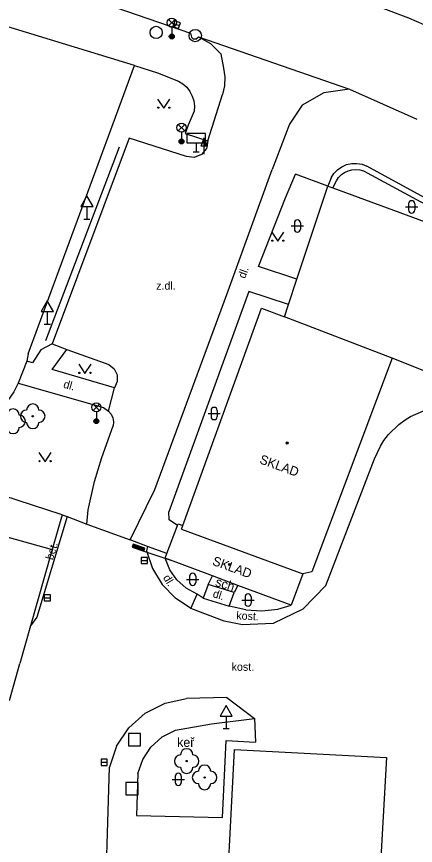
# Model space of a CAD drawing. Extents: x -598233 to -596890, y -1157848 to -1156431.
# Drawn here: x -598107.9 to -598075.5, y -1157490.1 to -1157422.8 of the extents above; entities that cross this region are included whole.
import ezdxf

# ---------------------------------------------------------------- set-up
doc = ezdxf.new("R2010")
doc.units = 0
for name, color, linetype in [('Level 10', 7, 'Continuous'), ('Level 11', 7, 'Continuous'), ('Level 22', 7, 'Continuous'), ('Level 25', 7, 'Continuous'), ('Level 26', 7, 'Continuous'), ('Level 27', 7, 'Continuous'), ('Level 33', 7, 'Continuous'), ('Level 34', 7, 'Continuous'), ('Level 36', 7, 'Continuous'), ('Level 39', 7, 'Continuous'), ('Level 40', 7, 'Continuous'), ('Level 41', 7, 'Continuous'), ('Level 42', 7, 'Continuous'), ('Level 5', 7, 'Continuous'), ('Level 7', 7, 'Continuous'), ('Level 8', 7, 'Continuous')]:
    doc.layers.add(name, color=color, linetype=linetype)

msp = doc.modelspace()

# ---------------------------------------------------------------- linework, layer by layer
at = {"layer": 'Level 10'}
for points in [[(-598122.65, -1157415.04), (-598121.35, -1157414.91), (-598120.33, -1157414.94), (-598106.78, -1157419.65), (-598093.77, -1157424.14)], [(-598076.03, -1157422.91), (-598078.56, -1157421.96)], [(-598073.53, -1157423.99), (-598076.03, -1157422.91)], [(-598093.77, -1157424.14), (-598093.71, -1157424.45)], [(-598093.35, -1157424.62), (-598093.54, -1157424.63), (-598093.71, -1157424.45)], [(-598093.35, -1157424.62), (-598093.12, -1157424.44)], [(-598093.12, -1157424.44), (-598092.16, -1157424.96)], [(-598092.16, -1157424.96), (-598091.32, -1157425.82)], [(-598091.32, -1157425.82), (-598091.09, -1157426.97)], [(-598091.09, -1157426.9699), (-598090.99, -1157427.69), (-598091.02, -1157428.4099), (-598091.19, -1157429.12)], [(-598080.85, -1157428.69), (-598082.95, -1157428.98)], [(-598080.85, -1157428.69), (-598075.38, -1157431.12)], [(-598092.38, -1157432.87), (-598091.19, -1157429.12)], [(-598082.95, -1157428.98), (-598084.71, -1157429.98)], [(-598084.71, -1157429.98), (-598085.73, -1157431.52), (-598087.13, -1157435.2)], [(-598094.1, -1157434.15), (-598098.77, -1157432.65), (-598105.01, -1157449.35)], [(-598092.48, -1157433.5), (-598092.88, -1157433.99), (-598093.47, -1157434.23), (-598094.1, -1157434.15)], [(-598092.38, -1157432.87), (-598092.48, -1157433.5)], [(-598090.83, -1157445.34), (-598087.13, -1157435.2)], [(-598096.67, -1157461.19), (-598090.83, -1157445.34)], [(-598105.01, -1157449.35), (-598103.84, -1157449.82)], [(-598103.84, -1157449.82), (-598100.41, -1157451.03)], [(-598100.41, -1157451.03), (-598099.98, -1157451.38), (-598099.74, -1157451.87)], [(-598099.74, -1157451.87), (-598099.73, -1157452.42), (-598099.95, -1157452.92)], [(-598100.43, -1157454.82), (-598099.95, -1157452.92)], [(-598100.43, -1157454.82), (-598100.23, -1157455.08), (-598100.1, -1157455.38), (-598100.05, -1157455.7), (-598100.07, -1157456.03)], [(-598078.83, -1157458.71), (-598078.34, -1157457.6599), (-598078.07, -1157457.2), (-598077.68, -1157456.7199), (-598076.85, -1157455.9099), (-598076.34, -1157455.53), (-598075.9, -1157455.26), (-598074.85, -1157454.79), (-598073.73, -1157454.51), (-598072.58, -1157454.44), (-598071.44, -1157454.57)], [(-598102.21, -1157464.01), (-598102.09, -1157462.85), (-598101.59, -1157460.53), (-598100.98, -1157458.58), (-598100.07, -1157456.03)], [(-598082.77, -1157468.99), (-598078.83, -1157458.71)], [(-598098.68, -1157465.28), (-598096.67, -1157461.19)], [(-598103.81, -1157463.38), (-598106.28, -1157471.55), (-598106.77, -1157472.27)], [(-598097.26, -1157465.81), (-598097.36, -1157466.18)], [(-598097.36, -1157466.18), (-598096.86, -1157467.61), (-598096.07, -1157468.91), (-598095.01, -1157470.01)], [(-598082.77, -1157468.99), (-598084.6599, -1157470.9), (-598087.07, -1157472.07)], [(-598093.75, -1157470.85), (-598095.01, -1157470.01)], [(-598089.54, -1157472.19), (-598091.05, -1157471.89), (-598093.75, -1157470.85)], [(-598087.07, -1157472.07), (-598089.54, -1157472.19)], [(-598099.78, -1157482.03), (-598098.79, -1157480.54), (-598097.45, -1157479.35), (-598095.85, -1157478.54), (-598094.1, -1157478.16)], [(-598090.82, -1157478.08), (-598094.1, -1157478.16)], [(-598099.78, -1157482.03), (-598100.36, -1157483.73)], [(-598100.77, -1157497.17), (-598100.36, -1157483.73)]]:
    msp.add_lwpolyline(points, dxfattribs=at)
at = {"layer": 'Level 11'}
for points in [[(-598093.12, -1157424.44), (-598080.85, -1157428.69)], [(-598098.33, -1157426.76), (-598096.46, -1157427.35), (-598094.75, -1157428.02)], [(-598094.75, -1157428.02), (-598094.4, -1157428.25), (-598094.09, -1157428.53), (-598093.83, -1157428.86), (-598093.64, -1157429.24), (-598093.51, -1157429.63), (-598093.45, -1157430.05), (-598093.4699, -1157430.4699)], [(-598093.47, -1157430.47), (-598093.98, -1157431.61)], [(-598093.98, -1157431.61), (-598094.2, -1157432.28)], [(-598094.2, -1157432.28), (-598092.38, -1157432.87)], [(-598082.34, -1157435.88), (-598082.12, -1157435.53), (-598081.82, -1157435.23), (-598081.48, -1157434.98), (-598081.09, -1157434.81), (-598080.68, -1157434.7199), (-598080.26, -1157434.71), (-598079.84, -1157434.78), (-598079.45, -1157434.93)], [(-598081.92, -1157436.12), (-598081.74, -1157435.85), (-598081.52, -1157435.62), (-598081.26, -1157435.44), (-598080.9699, -1157435.31), (-598080.67, -1157435.23), (-598080.35, -1157435.2), (-598080.03, -1157435.23), (-598079.73, -1157435.32)], [(-598079.73, -1157435.32), (-598068.09, -1157441.59)], [(-598067.87, -1157441.24), (-598079.45, -1157434.93)], [(-598085.13, -1157444.11), (-598088.24, -1157443.07), (-598086.06, -1157437.51), (-598085.25, -1157435.58)], [(-598082.61, -1157436.55), (-598085.25, -1157435.58)], [(-598082.34, -1157435.88), (-598082.61, -1157436.55)], [(-598082.2, -1157436.7), (-598081.92, -1157436.12)], [(-598089.04, -1157445.1), (-598095.55, -1157462.99)], [(-598085.82, -1157446.17), (-598089.04, -1157445.1)], [(-598105.01, -1157449.35), (-598105.94, -1157449.85), (-598106.62, -1157450.9), (-598107.09, -1157450.76)], [(-598099.95, -1157452.92), (-598105.02, -1157451.44), (-598103.84, -1157449.82)], [(-598107.78, -1157452.55), (-598100.86, -1157454.53), (-598100.43, -1157454.82)], [(-598094.83, -1157464.11), (-598095.51, -1157463.64), (-598095.55, -1157462.99)], [(-598113.58, -1157463.69), (-598105.02, -1157466.07)], [(-598093.25, -1157469.68), (-598094.14, -1157469.2), (-598094.89, -1157468.53), (-598095.47, -1157467.7), (-598095.85, -1157466.77)], [(-598092.33, -1157468.89), (-598091.99, -1157468.2)], [(-598092.33, -1157468.89), (-598092.74, -1157470.01), (-598093.25, -1157469.68)], [(-598090.24, -1157469.55), (-598092.33, -1157468.89)], [(-598089.93, -1157468.97), (-598090.24, -1157469.55)], [(-598093.75, -1157470.85), (-598093.25, -1157469.68)], [(-598089.28, -1157470.97), (-598090.63, -1157470.67), (-598090.24, -1157469.55)], [(-598092.74, -1157470.01), (-598090.63, -1157470.67)], [(-598089.28, -1157470.97), (-598087.98, -1157471.03), (-598086.69, -1157470.91), (-598085.6, -1157470.58)], [(-598090.82, -1157478.08), (-598088.59, -1157479.77), (-598088.5, -1157481.7)], [(-598095.01, -1157480.72), (-598092.07, -1157480.21), (-598088.59, -1157479.77)], [(-598098.05, -1157484.26), (-598097.65, -1157483.11), (-598096.99, -1157482.1), (-598096.09, -1157481.28), (-598095.01, -1157480.72)], [(-598098.05, -1157484.26), (-598098.18, -1157487.66), (-598091.19, -1157487.83), (-598090.87, -1157481.58), (-598088.5, -1157481.7)]]:
    msp.add_lwpolyline(points, dxfattribs=at)
at = {"layer": 'Level 22'}
for centre in [(-598106.6, -1157455.24), (-598094.09, -1157483.24), (-598092.63, -1157484.57)]:
    msp.add_circle(centre, 0.05, dxfattribs=at)
for centre, start, end in [((-598106.6, -1157454.74), 0, 180), ((-598108.2, -1157455.15), 0, 180), ((-598107.1, -1157455.24), 90, 270), ((-598106.1, -1157455.24), 270, 90), ((-598107.7, -1157455.65), 270, 90), ((-598108.2, -1157456.15), 180, 0), ((-598106.6, -1157455.74), 180, 0), ((-598094.09, -1157482.74), 0, 180), ((-598094.59, -1157483.24), 90, 270), ((-598093.59, -1157483.24), 270, 90), ((-598094.09, -1157483.74), 180, 0), ((-598092.63, -1157484.07), 0, 180), ((-598093.13, -1157484.57), 90, 270), ((-598092.13, -1157484.57), 270, 90), ((-598092.63, -1157485.07), 180, 0)]:
    msp.add_arc(centre, 0.5, start, end, dxfattribs=at)
at = {"layer": 'Level 25'}
for p, q in [((-598092.922, -1157433.298), (-598092.67, -1157432.624)), ((-598092.67, -1157433.298), (-598092.922, -1157433.298)), ((-598092.67, -1157433.95), (-598092.67, -1157433.3))]:
    msp.add_line(p, q, dxfattribs=at)
for points in [[(-598092.42, -1157433.3), (-598092.67, -1157433.3), (-598092.67, -1157432.624), (-598092.67, -1157432.624)], [(-598092.477, -1157433.26), (-598092.63, -1157433.26), (-598092.63, -1157432.847)], [(-598092.535, -1157433.22), (-598092.59, -1157433.22), (-598092.59, -1157433.071)]]:
    msp.add_lwpolyline(points, close=True, dxfattribs=at)
at = {"layer": 'Level 26'}
for points in [[(-598098.83, -1157482.01), (-598097.83, -1157482.01), (-598097.83, -1157481.01), (-598098.83, -1157481.01)], [(-598099.03, -1157485.98), (-598098.03, -1157485.98), (-598098.03, -1157484.98), (-598099.03, -1157484.98)]]:
    msp.add_lwpolyline(points, close=True, dxfattribs=at)
at = {"layer": 'Level 27'}
for p, q in [((-598095.1358, -1157423.357), (-598094.6642, -1157423.523)), ((-598097.78, -1157466.96), (-598097.28, -1157466.96)), ((-598105.66, -1157469.98), (-598105.16, -1157469.98)), ((-598101.05, -1157483.34), (-598100.55, -1157483.34))]:
    msp.add_line(p, q, dxfattribs=at)
for points in [[(-598095.2188, -1157423.5928), (-598094.7472, -1157423.7588), (-598094.5812, -1157423.2872), (-598095.0528, -1157423.1212)], [(-598097.78, -1157467.21), (-598097.28, -1157467.21), (-598097.28, -1157466.71), (-598097.78, -1157466.71)], [(-598105.66, -1157470.23), (-598105.16, -1157470.23), (-598105.16, -1157469.73), (-598105.66, -1157469.73)], [(-598101.05, -1157483.59), (-598100.55, -1157483.59), (-598100.55, -1157483.09), (-598101.05, -1157483.09)]]:
    msp.add_lwpolyline(points, close=True, dxfattribs=at)
for centre in [(-598096.57, -1157424.07), (-598093.39, -1157424.33)]:
    msp.add_circle(centre, 0.5, dxfattribs=at)
at = {"layer": 'Level 33'}
for p, q in [((-598095.565, -1157423.5499), (-598095.035, -1157423.0199)), ((-598095.565, -1157423.0199), (-598095.035, -1157423.5499)), ((-598095.3, -1157423.6599), (-598095.3, -1157424.4099)), ((-598094.775, -1157432.07), (-598094.245, -1157431.54)), ((-598094.775, -1157431.54), (-598094.245, -1157432.07)), ((-598094.51, -1157432.18), (-598094.51, -1157432.93)), ((-598101.695, -1157454.78), (-598101.165, -1157454.25)), ((-598101.695, -1157454.25), (-598101.165, -1157454.78)), ((-598101.43, -1157454.89), (-598101.43, -1157455.64)), ((-598097.5738, -1157466.1837), (-598095.2084, -1157466.9929))]:
    msp.add_line(p, q, dxfattribs=at)
for points in [[(-598098.52, -1157465.86), (-598097.5738, -1157466.1837), (-598097.4929, -1157465.9472), (-598098.4391, -1157465.6235)], [(-598098.4565, -1157465.8289), (-598097.605, -1157466.1202), (-598097.5564, -1157465.9783), (-598098.408, -1157465.687)], [(-598098.393, -1157465.7978), (-598097.6361, -1157466.0567), (-598097.6199, -1157466.0094), (-598098.3768, -1157465.7504)]]:
    msp.add_lwpolyline(points, close=True, dxfattribs=at)
for centre, radius in [((-598095.3, -1157423.2849), 0.375), ((-598095.3, -1157424.4099), 0.2), ((-598095.3, -1157424.4099), 0.1445), ((-598095.3, -1157424.4099), 0.0876), ((-598094.51, -1157431.805), 0.375), ((-598094.51, -1157432.93), 0.2), ((-598094.51, -1157432.93), 0.1445), ((-598094.51, -1157432.93), 0.0876), ((-598101.43, -1157454.515), 0.375), ((-598101.43, -1157455.64), 0.2), ((-598101.43, -1157455.64), 0.1445), ((-598101.43, -1157455.64), 0.0876)]:
    msp.add_circle(centre, radius, dxfattribs=at)
at = {"layer": 'Level 34'}
for p, q in [((-598093.32, -1157433.03), (-598093.32, -1157433.78)), ((-598093.57, -1157433.78), (-598093.07, -1157433.78)), ((-598102.2, -1157438.212), (-598102.2, -1157439.23)), ((-598102.45, -1157439.23), (-598101.95, -1157439.23)), ((-598105.42, -1157446.732), (-598105.42, -1157447.75)), ((-598105.67, -1157447.75), (-598105.17, -1157447.75)), ((-598090.88, -1157479.582), (-598090.88, -1157480.6)), ((-598091.13, -1157480.6), (-598090.63, -1157480.6))]:
    msp.add_line(p, q, dxfattribs=at)
for points in [[(-598094.07, -1157433.03), (-598092.57, -1157433.03), (-598092.57, -1157432.28), (-598094.07, -1157432.28)], [(-598102.7, -1157438.212), (-598101.7, -1157438.212), (-598102.2, -1157437.346)], [(-598105.92, -1157446.732), (-598104.92, -1157446.732), (-598105.42, -1157445.866)], [(-598091.38, -1157479.582), (-598090.38, -1157479.582), (-598090.88, -1157478.716)]]:
    msp.add_lwpolyline(points, close=True, dxfattribs=at)
at = {"layer": 'Level 36'}
for p, q in [((-598076.056, -1157437.986), (-598076.056, -1157438.486)), ((-598075.556, -1157437.986), (-598075.556, -1157438.486)), ((-598076.306, -1157438.236), (-598075.306, -1157438.236)), ((-598085.336, -1157439.536), (-598085.336, -1157440.036)), ((-598084.836, -1157439.536), (-598084.836, -1157440.036)), ((-598085.586, -1157439.786), (-598084.586, -1157439.786)), ((-598092.356, -1157455.016), (-598091.356, -1157455.016)), ((-598092.106, -1157454.766), (-598092.106, -1157455.266)), ((-598091.606, -1157454.766), (-598091.606, -1157455.266)), ((-598094.106, -1157468.486), (-598093.106, -1157468.486)), ((-598093.856, -1157468.236), (-598093.856, -1157468.736)), ((-598093.356, -1157468.236), (-598093.356, -1157468.736)), ((-598089.596, -1157470.166), (-598088.596, -1157470.166)), ((-598089.346, -1157469.916), (-598089.346, -1157470.416)), ((-598088.846, -1157469.916), (-598088.846, -1157470.416)), ((-598095.026, -1157484.476), (-598095.026, -1157484.976)), ((-598094.526, -1157484.476), (-598094.526, -1157484.976)), ((-598095.276, -1157484.726), (-598094.276, -1157484.726))]:
    msp.add_line(p, q, dxfattribs=at)
for points in [[(-598096.45, -1157429.48), (-598095.95, -1157430.23), (-598095.45, -1157429.48)], [(-598087.18, -1157440.28), (-598086.68, -1157441.03), (-598086.18, -1157440.28)], [(-598102.86, -1157451.02), (-598102.36, -1157451.77), (-598101.86, -1157451.02)], [(-598106.1, -1157458.19), (-598105.6, -1157458.94), (-598105.1, -1157458.19)]]:
    msp.add_lwpolyline(points, dxfattribs=at)
for centre in [(-598096.4002, -1157430.1798), (-598095.5008, -1157430.1798), (-598087.1302, -1157440.9798), (-598086.2308, -1157440.9798), (-598102.8102, -1157451.7198), (-598101.9108, -1157451.7198), (-598106.0502, -1157458.8898), (-598105.1508, -1157458.8898)]:
    msp.add_circle(centre, 0.05, dxfattribs=at)
for centre, start, end in [((-598075.8057, -1157437.9863), 0, 180), ((-598075.8057, -1157438.4863), 180, 0), ((-598085.0857, -1157439.5363), 0, 180), ((-598085.0857, -1157440.0363), 180, 0), ((-598091.8557, -1157454.7663), 0, 180), ((-598091.8557, -1157455.2663), 180, 0), ((-598093.6057, -1157468.2363), 0, 180), ((-598093.6057, -1157468.7363), 180, 0), ((-598089.0957, -1157469.9163), 0, 180), ((-598089.0957, -1157470.4163), 180, 0), ((-598094.7757, -1157484.4763), 0, 180), ((-598094.7757, -1157484.9763), 180, 0)]:
    msp.add_arc(centre, 0.25, start, end, dxfattribs=at)
at = {"layer": 'Level 39'}
for centre, radius in [((-598085.92, -1157457.42), 0.09), ((-598085.92, -1157457.42), 0.0398), ((-598090.61, -1157467.28), 0.09), ((-598090.61, -1157467.28), 0.0398)]:
    msp.add_circle(centre, radius, dxfattribs=at)
at = {"layer": 'Level 5'}
for points in [[(-598086.15, -1157447.17), (-598085.82, -1157446.17), (-598085.13, -1157444.11), (-598082.61, -1157436.55)], [(-598082.61, -1157436.55), (-598082.2, -1157436.7)], [(-598082.2, -1157436.7), (-598068.2199, -1157441.83)], [(-598094.39, -1157464.11), (-598088.02, -1157446.4699)], [(-598088.02, -1157446.4699), (-598086.15, -1157447.17)], [(-598077.4, -1157450.53), (-598086.15, -1157447.17)], [(-598077.4, -1157450.53), (-598083.9099, -1157467.88)], [(-598066.08, -1157455.02), (-598077.4, -1157450.53)], [(-598095.85, -1157466.77), (-598095.7, -1157466.39), (-598094.83, -1157464.11), (-598094.78, -1157463.9699)], [(-598094.78, -1157463.9699), (-598094.39, -1157464.11)], [(-598094.5, -1157464.4099), (-598094.39, -1157464.11)], [(-598094.5, -1157464.4099), (-598084.6599, -1157468.04)], [(-598085.6, -1157470.58), (-598089.93, -1157468.97), (-598091.99, -1157468.2), (-598095.85, -1157466.77)], [(-598084.6599, -1157468.04), (-598085.6, -1157470.58)], [(-598083.9099, -1157467.88), (-598084.6599, -1157468.04)], [(-598091.03, -1157498.54), (-598090.21, -1157482.31)], [(-598090.21, -1157482.31), (-598077.85, -1157482.94)], [(-598077.85, -1157482.94), (-598078.74, -1157498.76)]]:
    msp.add_lwpolyline(points, dxfattribs=at)
at = {"layer": 'Level 7'}
for points in [[(-598098.33, -1157426.76), (-598124.68, -1157418.7)], [(-598100.25, -1157431.97), (-598098.33, -1157426.76)], [(-598106.97, -1157450.17), (-598100.25, -1157431.97)], [(-598105.53, -1157449.08), (-598099.56, -1157433.36)], [(-598107.78, -1157452.55), (-598108.14, -1157453.25), (-598109.38, -1157455.01), (-598111.63, -1157457.09)], [(-598104.22, -1157463.24), (-598112.64, -1157460.5)], [(-598104.22, -1157463.24), (-598105.02, -1157466.07), (-598106.77, -1157472.27), (-598107.66, -1157475.33)], [(-598104.22, -1157463.24), (-598103.81, -1157463.38), (-598102.21, -1157464.01)], [(-598095.7, -1157466.39), (-598097.26, -1157465.81), (-598098.68, -1157465.28)]]:
    msp.add_lwpolyline(points, dxfattribs=at)
at = {"layer": 'Level 8'}
for points in [[(-598106.97, -1157450.17), (-598107.09, -1157450.76), (-598107.78, -1157452.55)], [(-598102.21, -1157464.01), (-598098.68, -1157465.28)], [(-598108.5, -1157478.31), (-598107.66, -1157475.33)]]:
    msp.add_lwpolyline(points, dxfattribs=at)

# ---------------------------------------------------------------- texts
at = {"layer": 'Level 40'}
for s, rotation, p in [('dl.', 70, (-598089.34, -1157444.1)), ('dl.', 344, (-598104.16, -1157452.91)), ('bet.', 73.17859, (-598104.96, -1157466.96)), ('dl.', 301, (-598096.04, -1157468.34)), ('dl.', 342.630515, (-598092.02, -1157469.91)), ('kost.', 357, (-598090.07, -1157471.73))]:
    msp.add_text(s, height=0.65, rotation=rotation, dxfattribs=at).set_placement(p)
for s, p in [('z.dl.', (-598096.57, -1157444.96)), ('kost.', (-598090.44, -1157475.91))]:
    msp.add_text(s, height=0.65, dxfattribs=at).set_placement(p)
at = {"layer": 'Level 41'}
for p in [(-598088.23, -1157459.04), (-598092.06, -1157467.29)]:
    msp.add_text('SKLAD', height=0.75, rotation=340, dxfattribs=at).set_placement(p)
at = {"layer": 'Level 42'}
msp.add_text('sch.', height=0.75, rotation=342.474432, dxfattribs=at).set_placement((-598091.82, -1157469))
msp.add_text('keř', height=0.75, dxfattribs=at).set_placement((-598094.86, -1157482.09))

doc.saveas('drawing.dxf')
